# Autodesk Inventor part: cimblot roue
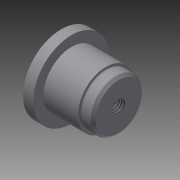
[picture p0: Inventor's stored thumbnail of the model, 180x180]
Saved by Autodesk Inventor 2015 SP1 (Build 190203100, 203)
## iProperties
Created: 2015-01
Part Number: cimblot roue
Material: Générique
Document SubType Name: Modeling
Designer: Dominique
Density: 1 g/cm^3
Appearance: Par défaut
Author: Dominique
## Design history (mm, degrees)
sketch "Esquisse1"
  geometry: L1 (0, 0)-(-13.5, 0); L2 (-13.5, 11)-(0, 11); L3 (0, 11)-(0, 10.5); L4 (-13.5, 0)-(-17.5, 0); L5 (-17.5, 0)-(-17.5, 15); L6 (-17.5, 15)-(-13.5, 15); L7 (-13.5, 15)-(-13.5, 11); L8 (0, 0)-(5, 0); L9 (5, 0)-(5, 9); L10 (4, 10)-(0.5, 10); L11 (5, 9)-(4, 10); A1 r 0.5 centre (0.5, 10.5) between (0, 10.5) and (0.5, 10); 1 further point
  constraints: 22 end point, 4 parallel, 3 horizontal, 2 perpendicular, 2 point on circle, 2 point on line, 2 tangent, 1 centre point
  dimensions: "d4" = 11 distance between parallel lines of L1 L2; "d5" = 15 distance between parallel lines of L1 L6; "d6" = 4 distance between parallel lines of L7 L5; "d10" = 5 distance from line of L9 L1.start; "d11" = 10 distance between parallel lines of L10 L8; "d12" = 1 distance of L9.end point (5, 10); "d13" = 1 distance of L10.start point (5, 10) (= d12); "d14" = 0.5 radius of A1
revolve "Révolution1" sketch "Esquisse1" stored, may be unused: angle "d15" = 90 deg
sketch "Esquisse2"
  geometry: 1 further point
hole "Perçage1" sketch "Esquisse2" at (0, 0) diameter "d16" = 4.917; stored, may be unused: countersink angle "d20" = 90 deg, drill point angle "d22" = 118 deg; dims "d17" = 12, "d18" = 4, "d19" = 2, "d21" = 15
node "Solide1"
